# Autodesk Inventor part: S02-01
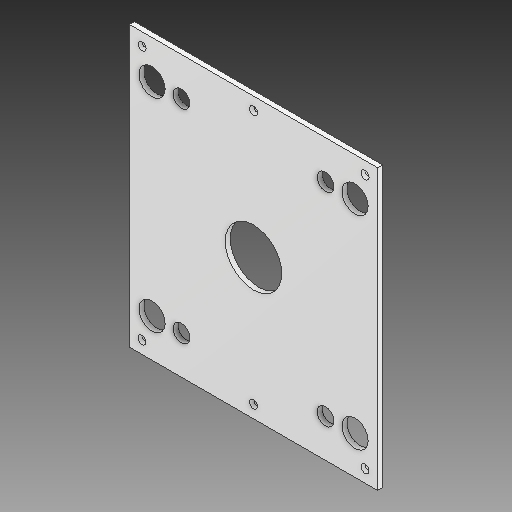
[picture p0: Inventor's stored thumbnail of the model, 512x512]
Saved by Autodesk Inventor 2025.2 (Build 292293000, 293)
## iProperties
Created: 2025-04
Part Number: S02-01
Material: Všeobecné
Document SubType Name: Modeling
Designer: Patrik
Density: 1 g/cm^3
Appearance: Výchozí
Description: Deska izolační pravá
Stock Number: E 1402/446 396/324/230/324
Author: Patrik
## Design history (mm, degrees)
feature "Base1"
node "Těleso1"
